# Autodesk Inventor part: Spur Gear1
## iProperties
Created: 2008-01
Part Number: Spur Gear1
Material: Steel
Document SubType Name: Modeling
Designer: eruiz-tagle
Mass: 4.25267 g
Surface Area: 7.20162 cm^2
Volume: 0.541741 cm^3
Density: 7.85 g/cm^3
CustomPartVersion: 1
Author: eruiz-tagle
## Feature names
1. Extrusion1
2. Chamfer1
3. Chamfer2
